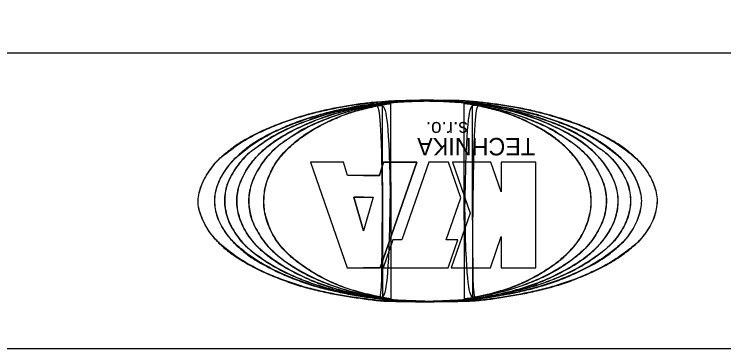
# Model space of a CAD drawing. Extents: x -728476.8 to -728424.3, y -1073086.9 to -1073012.7.
# Drawn here: x -728468.69 to -728456.69, y -1073048.15 to -1073042.49 of the extents above; entities that cross this region are included whole.
import ezdxf

# ---------------------------------------------------------------- set-up
doc = ezdxf.new("R2010")
doc.units = 0
doc.layers.add('A1_OBVOD Spravy železnic', color=7, linetype='Continuous')
doc.layers.add('B6_JŽM', color=7, linetype='Continuous')

msp = doc.modelspace()

# ---------------------------------------------------------------- linework, layer by layer
at = {"layer": 'A1_OBVOD Spravy železnic'}
msp.add_line((-728429.288, -1073043.154), (-728471.788, -1073043.154), dxfattribs=at)
msp.add_lwpolyline([(-728429.288, -1073048.154), (-728471.788, -1073048.154), (-728471.788, -1073035.654), (-728429.288, -1073035.654)], close=True, dxfattribs=at)
at = {"layer": 'B6_JŽM'}
for p, q in [((-728462.947, -1073045.587), (-728462.781, -1073045.587)), ((-728462.781, -1073046.161), (-728462.947, -1073045.587))]:
    msp.add_line(p, q, dxfattribs=at)
for points in [[(-728462.781, -1073045.225), (-728463.051, -1073045.225), (-728463.117, -1073044.997), (-728463.68, -1073044.998), (-728463.059, -1073046.782), (-728462.781, -1073046.782)], [(-728462.781, -1073045.225), (-728463.051, -1073045.225), (-728463.117, -1073044.997), (-728463.68, -1073044.998), (-728463.059, -1073046.782), (-728462.781, -1073046.782)], [(-728462.781, -1073045.225), (-728462.51, -1073045.225), (-728462.444, -1073044.997), (-728461.881, -1073044.998), (-728462.502, -1073046.782), (-728462.781, -1073046.782)], [(-728462.781, -1073046.782), (-728462.502, -1073046.782), (-728461.881, -1073044.998), (-728462.444, -1073044.997), (-728462.51, -1073045.225), (-728462.781, -1073045.225)], [(-728461.351, -1073046.782), (-728461.187, -1073046.311), (-728461.381, -1073046.311), (-728461.134, -1073045.601), (-728461.344, -1073044.997), (-728461.676, -1073044.997), (-728462.133, -1073046.311), (-728462.284, -1073046.311), (-728462.449, -1073046.782), (-728461.351, -1073046.782)], [(-728461.351, -1073046.782), (-728461.187, -1073046.311), (-728461.381, -1073046.311), (-728461.134, -1073045.601), (-728461.344, -1073044.997), (-728461.676, -1073044.997), (-728462.133, -1073046.311), (-728462.284, -1073046.311), (-728462.449, -1073046.782), (-728461.351, -1073046.782)], [(-728459.867, -1073046.782), (-728459.867, -1073044.997), (-728460.451, -1073044.997), (-728460.451, -1073045.5), (-728460.626, -1073044.997), (-728461.276, -1073044.997), (-728460.976, -1073045.859), (-728461.297, -1073046.782), (-728460.635, -1073046.782), (-728460.451, -1073046.253), (-728460.451, -1073046.782), (-728459.867, -1073046.782)], [(-728459.867, -1073046.782), (-728459.867, -1073044.997), (-728460.451, -1073044.997), (-728460.451, -1073045.5), (-728460.626, -1073044.997), (-728461.276, -1073044.997), (-728460.976, -1073045.859), (-728461.297, -1073046.782), (-728460.635, -1073046.782), (-728460.451, -1073046.253), (-728460.451, -1073046.782), (-728459.867, -1073046.782)], [(-728462.781, -1073045.587), (-728462.947, -1073045.587), (-728462.781, -1073046.161)], [(-728462.781, -1073045.587), (-728462.615, -1073045.587), (-728462.781, -1073046.161)], [(-728462.781, -1073045.587), (-728462.615, -1073045.587), (-728462.781, -1073046.161)]]:
    msp.add_lwpolyline(points, dxfattribs=at)
for points in [[(-728462.313, -1073043.965), (-728462.376, -1073043.969), (-728462.529, -1073043.98), (-728462.771, -1073044), (-728463.038, -1073044.044), (-728463.307, -1073044.089), (-728463.576, -1073044.15), (-728463.845, -1073044.224), (-728464.113, -1073044.313), (-728464.382, -1073044.416), (-728464.653, -1073044.542), (-728464.929, -1073044.699), (-728465.125, -1073044.86), (-728465.283, -1073044.992), (-728465.368, -1073045.112), (-728465.461, -1073045.242), (-728465.521, -1073045.38), (-728465.567, -1073045.514), (-728465.592, -1073045.65), (-728465.574, -1073045.789), (-728465.523, -1073045.921), (-728465.466, -1073046.059), (-728465.382, -1073046.195), (-728465.284, -1073046.308), (-728465.134, -1073046.456), (-728464.928, -1073046.611), (-728464.655, -1073046.771), (-728464.385, -1073046.901), (-728464.114, -1073047.001), (-728463.847, -1073047.097), (-728463.576, -1073047.164), (-728463.308, -1073047.226), (-728463.038, -1073047.272), (-728462.769, -1073047.307), (-728462.502, -1073047.348), (-728462.234, -1073047.351), (-728461.966, -1073047.357), (-728461.788, -1073047.358), (-728461.698, -1073047.359)], [(-728461.698, -1073047.359), (-728461.395, -1073047.355), (-728461.162, -1073047.352), (-728460.894, -1073047.341), (-728460.626, -1073047.312), (-728460.358, -1073047.27), (-728460.09, -1073047.224), (-728459.822, -1073047.166), (-728459.554, -1073047.096), (-728459.285, -1073047.009), (-728459.017, -1073046.902), (-728458.751, -1073046.779), (-728458.482, -1073046.62), (-728458.214, -1073046.418), (-728458.11, -1073046.321), (-728458.001, -1073046.186), (-728457.919, -1073046.053), (-728457.859, -1073045.918), (-728457.827, -1073045.785), (-728457.811, -1073045.651), (-728457.825, -1073045.519), (-728457.866, -1073045.383), (-728457.926, -1073045.249), (-728458.01, -1073045.115), (-728458.118, -1073044.981), (-728458.214, -1073044.891), (-728458.482, -1073044.688), (-728458.75, -1073044.537), (-728459.015, -1073044.413), (-728459.286, -1073044.311), (-728459.555, -1073044.224), (-728459.821, -1073044.151), (-728460.088, -1073044.092), (-728460.357, -1073044.043), (-728460.626, -1073044.005), (-728460.895, -1073043.975), (-728461.16, -1073043.957), (-728461.43, -1073043.954), (-728461.698, -1073043.95), (-728461.966, -1073043.954), (-728462.235, -1073043.961), (-728462.503, -1073043.978), (-728462.769, -1073044.003), (-728463.038, -1073044.044), (-728463.306, -1073044.092), (-728463.574, -1073044.152), (-728463.843, -1073044.226), (-728464.111, -1073044.314), (-728464.379, -1073044.418), (-728464.645, -1073044.543), (-728464.915, -1073044.701), (-728465.185, -1073044.91), (-728465.265, -1073044.981), (-728465.37, -1073045.115), (-728465.458, -1073045.248), (-728465.52, -1073045.383), (-728465.564, -1073045.516), (-728465.585, -1073045.651), (-728465.57, -1073045.784), (-728465.523, -1073045.919), (-728465.463, -1073046.056), (-728465.383, -1073046.186), (-728465.269, -1073046.321), (-728465.187, -1073046.402), (-728464.916, -1073046.612), (-728464.648, -1073046.77), (-728464.382, -1073046.897), (-728464.112, -1073047.001), (-728463.843, -1073047.093), (-728463.576, -1073047.163), (-728463.306, -1073047.224), (-728463.037, -1073047.27), (-728462.768, -1073047.308), (-728462.502, -1073047.342), (-728462.234, -1073047.352), (-728461.967, -1073047.356), (-728461.698, -1073047.359), (-728461.698, -1073047.359), (-728461.698, -1073047.359)], [(-728461.698, -1073047.352), (-728461.788, -1073047.348), (-728461.967, -1073047.341), (-728462.235, -1073047.338), (-728462.503, -1073047.309), (-728462.771, -1073047.275), (-728463.04, -1073047.23), (-728463.307, -1073047.171), (-728463.578, -1073047.107), (-728463.845, -1073047.015), (-728464.116, -1073046.912), (-728464.383, -1073046.78), (-728464.662, -1073046.63), (-728464.867, -1073046.466), (-728465.02, -1073046.314), (-728465.116, -1073046.192), (-728465.198, -1073046.057), (-728465.26, -1073045.922), (-728465.292, -1073045.785), (-728465.303, -1073045.65), (-728465.293, -1073045.514), (-728465.252, -1073045.379), (-728465.192, -1073045.244), (-728465.107, -1073045.11), (-728465.016, -1073044.991), (-728464.861, -1073044.846), (-728464.662, -1073044.681), (-728464.385, -1073044.525), (-728464.114, -1073044.4), (-728463.845, -1073044.295), (-728463.576, -1073044.211), (-728463.308, -1073044.136), (-728463.039, -1073044.081), (-728462.771, -1073044.032), (-728462.502, -1073044.005), (-728462.234, -1073043.982), (-728461.967, -1073043.965), (-728461.698, -1073043.956), (-728461.43, -1073043.967), (-728461.162, -1073043.986), (-728460.893, -1073044), (-728460.625, -1073044.032), (-728460.356, -1073044.076), (-728460.088, -1073044.133), (-728459.818, -1073044.199), (-728459.552, -1073044.291), (-728459.281, -1073044.388), (-728459.009, -1073044.512), (-728458.74, -1073044.675), (-728458.528, -1073044.835), (-728458.367, -1073044.983), (-728458.27, -1073045.109), (-728458.191, -1073045.245), (-728458.13, -1073045.38), (-728458.093, -1073045.515), (-728458.069, -1073045.651), (-728458.09, -1073045.787), (-728458.125, -1073045.922), (-728458.181, -1073046.057), (-728458.261, -1073046.192), (-728458.357, -1073046.324), (-728458.525, -1073046.473), (-728458.736, -1073046.641), (-728459.014, -1073046.789), (-728459.281, -1073046.919), (-728459.55, -1073047.024), (-728459.819, -1073047.109), (-728460.088, -1073047.178), (-728460.317, -1073047.224), (-728460.497, -1073047.257), (-728460.675, -1073047.285), (-728460.893, -1073047.317), (-728461.162, -1073047.334), (-728461.43, -1073047.345), (-728461.609, -1073047.349), (-728461.698, -1073047.352)], [(-728461.698, -1073047.352), (-728461.43, -1073047.344), (-728461.162, -1073047.333), (-728460.894, -1073047.314), (-728460.626, -1073047.277), (-728460.506, -1073047.258), (-728460.358, -1073047.231), (-728460.09, -1073047.176), (-728459.822, -1073047.107), (-728459.553, -1073047.021), (-728459.285, -1073046.916), (-728459.017, -1073046.789), (-728458.751, -1073046.639), (-728458.482, -1073046.434), (-728458.363, -1073046.321), (-728458.26, -1073046.186), (-728458.183, -1073046.053), (-728458.127, -1073045.918), (-728458.092, -1073045.785), (-728458.077, -1073045.651), (-728458.095, -1073045.517), (-728458.133, -1073045.384), (-728458.192, -1073045.249), (-728458.27, -1073045.115), (-728458.376, -1073044.98), (-728458.482, -1073044.879), (-728458.75, -1073044.675), (-728459.017, -1073044.514), (-728459.285, -1073044.391), (-728459.553, -1073044.291), (-728459.821, -1073044.203), (-728460.089, -1073044.134), (-728460.357, -1073044.078), (-728460.626, -1073044.034), (-728460.894, -1073044.003), (-728461.162, -1073043.985), (-728461.43, -1073043.968), (-728461.698, -1073043.96), (-728461.966, -1073043.967), (-728462.235, -1073043.983), (-728462.501, -1073044.006), (-728462.769, -1073044.035), (-728463.038, -1073044.082), (-728463.306, -1073044.139), (-728463.574, -1073044.212), (-728463.843, -1073044.298), (-728464.111, -1073044.402), (-728464.379, -1073044.526), (-728464.647, -1073044.683), (-728464.915, -1073044.897), (-728465.001, -1073044.981), (-728465.108, -1073045.115), (-728465.19, -1073045.248), (-728465.251, -1073045.383), (-728465.289, -1073045.516), (-728465.3, -1073045.649), (-728465.288, -1073045.785), (-728465.256, -1073045.918), (-728465.197, -1073046.052), (-728465.116, -1073046.186), (-728465.009, -1073046.321), (-728464.915, -1073046.416), (-728464.647, -1073046.628), (-728464.379, -1073046.78), (-728464.111, -1073046.909), (-728463.843, -1073047.014), (-728463.575, -1073047.103), (-728463.307, -1073047.17), (-728463.039, -1073047.228), (-728462.77, -1073047.273), (-728462.502, -1073047.308), (-728462.235, -1073047.334), (-728461.967, -1073047.342), (-728461.698, -1073047.352), (-728461.698, -1073047.352), (-728461.698, -1073047.352)], [(-728461.698, -1073047.359), (-728461.597, -1073047.357), (-728461.419, -1073047.355), (-728461.15, -1073047.352), (-728460.893, -1073047.344), (-728460.625, -1073047.315), (-728460.358, -1073047.27), (-728460.089, -1073047.226), (-728459.82, -1073047.168), (-728459.551, -1073047.099), (-728459.282, -1073047.011), (-728459.015, -1073046.903), (-728458.743, -1073046.781), (-728458.472, -1073046.62), (-728458.261, -1073046.462), (-728458.1, -1073046.316), (-728458.001, -1073046.193), (-728457.918, -1073046.057), (-728457.855, -1073045.923), (-728457.825, -1073045.786), (-728457.805, -1073045.652), (-728457.822, -1073045.515), (-728457.864, -1073045.38), (-728457.924, -1073045.244), (-728458.012, -1073045.11), (-728458.106, -1073044.988), (-728458.264, -1073044.845), (-728458.469, -1073044.686), (-728458.744, -1073044.536), (-728459.012, -1073044.41), (-728459.283, -1073044.31), (-728459.552, -1073044.222), (-728459.82, -1073044.149), (-728460.088, -1073044.09), (-728460.356, -1073044.041), (-728460.626, -1073044.004), (-728460.893, -1073043.974), (-728461.162, -1073043.953), (-728461.43, -1073043.956), (-728461.698, -1073043.947), (-728461.966, -1073043.955), (-728462.171, -1073043.958), (-728462.287, -1073043.964), (-728462.313, -1073043.965)], [(-728462.458, -1073044.009), (-728462.509, -1073044.014), (-728462.614, -1073044.022), (-728462.809, -1073044.052), (-728463.041, -1073044.1), (-728463.312, -1073044.158), (-728463.579, -1073044.243), (-728463.848, -1073044.336), (-728464.118, -1073044.453), (-728464.392, -1073044.6), (-728464.582, -1073044.75), (-728464.752, -1073044.861), (-728464.852, -1073044.974), (-728464.954, -1073045.111), (-728465.034, -1073045.245), (-728465.096, -1073045.378), (-728465.123, -1073045.516), (-728465.138, -1073045.65), (-728465.123, -1073045.786), (-728465.092, -1073045.922), (-728465.04, -1073046.06), (-728464.957, -1073046.19), (-728464.861, -1073046.332), (-728464.751, -1073046.438), (-728464.591, -1073046.568), (-728464.389, -1073046.71), (-728464.118, -1073046.863), (-728463.846, -1073046.976), (-728463.579, -1073047.078), (-728463.309, -1073047.151), (-728463.038, -1073047.212), (-728462.771, -1073047.265), (-728462.577, -1073047.299), (-728462.473, -1073047.306), (-728462.459, -1073047.306)], [(-728462.458, -1073044.009), (-728462.611, -1073044.024), (-728462.772, -1073044.048), (-728463.04, -1073044.1), (-728463.309, -1073044.162), (-728463.578, -1073044.244), (-728463.845, -1073044.339), (-728464.112, -1073044.454), (-728464.381, -1073044.603), (-728464.65, -1073044.794), (-728464.722, -1073044.845), (-728464.854, -1073044.98), (-728464.955, -1073045.117), (-728465.033, -1073045.249), (-728465.091, -1073045.381), (-728465.121, -1073045.517), (-728465.133, -1073045.651), (-728465.121, -1073045.783), (-728465.09, -1073045.919), (-728465.037, -1073046.054), (-728464.958, -1073046.187), (-728464.862, -1073046.321), (-728464.725, -1073046.458), (-728464.652, -1073046.518), (-728464.381, -1073046.709), (-728464.11, -1073046.86), (-728463.843, -1073046.976), (-728463.578, -1073047.073), (-728463.304, -1073047.15), (-728463.039, -1073047.21), (-728462.769, -1073047.264), (-728462.501, -1073047.304), (-728462.459, -1073047.306), (-728462.458, -1073044.009), (-728462.459, -1073047.306)], [(-728462.459, -1073047.306), (-728462.555, -1073047.292), (-728462.749, -1073047.263), (-728463.033, -1073047.204), (-728463.31, -1073047.128), (-728463.58, -1073047.039), (-728463.848, -1073046.921), (-728464.118, -1073046.779), (-728464.355, -1073046.624), (-728464.541, -1073046.469), (-728464.665, -1073046.326), (-728464.763, -1073046.193), (-728464.835, -1073046.057), (-728464.887, -1073045.922), (-728464.917, -1073045.786), (-728464.927, -1073045.65), (-728464.917, -1073045.515), (-728464.883, -1073045.379), (-728464.825, -1073045.246), (-728464.755, -1073045.108), (-728464.654, -1073044.976), (-728464.531, -1073044.837), (-728464.352, -1073044.682), (-728464.118, -1073044.53), (-728463.846, -1073044.393), (-728463.577, -1073044.279), (-728463.31, -1073044.183), (-728463.04, -1073044.111), (-728462.797, -1073044.062), (-728462.603, -1073044.029), (-728462.498, -1073044.015), (-728462.458, -1073044.009)], [(-728462.459, -1073047.306), (-728462.748, -1073047.26), (-728463.038, -1073047.2), (-728463.308, -1073047.126), (-728463.577, -1073047.035), (-728463.842, -1073046.92), (-728464.11, -1073046.778), (-728464.379, -1073046.6), (-728464.547, -1073046.455), (-728464.667, -1073046.32), (-728464.762, -1073046.187), (-728464.833, -1073046.055), (-728464.884, -1073045.919), (-728464.914, -1073045.783), (-728464.923, -1073045.651), (-728464.913, -1073045.516), (-728464.88, -1073045.383), (-728464.825, -1073045.249), (-728464.753, -1073045.114), (-728464.655, -1073044.981), (-728464.536, -1073044.847), (-728464.376, -1073044.708), (-728464.111, -1073044.532), (-728463.842, -1073044.394), (-728463.574, -1073044.28), (-728463.306, -1073044.186), (-728463.039, -1073044.114), (-728462.77, -1073044.058), (-728462.58, -1073044.027), (-728462.458, -1073044.009), (-728462.459, -1073047.306), (-728462.458, -1073044.009)], [(-728462.318, -1073044.005), (-728462.379, -1073044.011), (-728462.532, -1073044.024), (-728462.771, -1073044.075), (-728463.042, -1073044.136), (-728463.309, -1073044.228), (-728463.579, -1073044.332), (-728463.853, -1073044.462), (-728464.055, -1073044.605), (-728464.235, -1073044.724), (-728464.353, -1073044.841), (-728464.475, -1073044.972), (-728464.558, -1073045.113), (-728464.635, -1073045.244), (-728464.687, -1073045.379), (-728464.715, -1073045.515), (-728464.73, -1073045.65), (-728464.714, -1073045.785), (-728464.693, -1073045.922), (-728464.637, -1073046.056), (-728464.565, -1073046.19), (-728464.478, -1073046.327), (-728464.365, -1073046.464), (-728464.237, -1073046.578), (-728464.062, -1073046.71), (-728463.851, -1073046.848), (-728463.58, -1073046.981), (-728463.31, -1073047.086), (-728463.042, -1073047.175), (-728462.772, -1073047.236), (-728462.532, -1073047.286), (-728462.379, -1073047.303), (-728462.318, -1073047.31)], [(-728462.318, -1073044.005), (-728462.502, -1073044.024), (-728462.771, -1073044.075), (-728463.037, -1073044.14), (-728463.306, -1073044.229), (-728463.575, -1073044.335), (-728463.842, -1073044.466), (-728464.111, -1073044.641), (-728464.212, -1073044.712), (-728464.358, -1073044.848), (-728464.473, -1073044.98), (-728464.559, -1073045.115), (-728464.633, -1073045.249), (-728464.684, -1073045.383), (-728464.713, -1073045.514), (-728464.725, -1073045.65), (-728464.713, -1073045.786), (-728464.688, -1073045.918), (-728464.637, -1073046.051), (-728464.564, -1073046.188), (-728464.479, -1073046.321), (-728464.367, -1073046.455), (-728464.22, -1073046.589), (-728464.11, -1073046.673), (-728463.842, -1073046.846), (-728463.576, -1073046.979), (-728463.306, -1073047.085), (-728463.04, -1073047.171), (-728462.772, -1073047.235), (-728462.502, -1073047.287), (-728462.318, -1073047.31), (-728462.318, -1073044.005), (-728462.318, -1073047.31)], [(-728462.318, -1073047.31), (-728462.379, -1073047.301), (-728462.532, -1073047.279), (-728462.772, -1073047.22), (-728463.043, -1073047.148), (-728463.313, -1073047.042), (-728463.583, -1073046.903), (-728463.819, -1073046.749), (-728464.012, -1073046.6), (-728464.148, -1073046.461), (-728464.254, -1073046.327), (-728464.335, -1073046.191), (-728464.393, -1073046.055), (-728464.437, -1073045.921), (-728464.465, -1073045.786), (-728464.469, -1073045.651), (-728464.461, -1073045.516), (-728464.435, -1073045.38), (-728464.387, -1073045.247), (-728464.328, -1073045.11), (-728464.243, -1073044.977), (-728464.137, -1073044.841), (-728464.001, -1073044.708), (-728463.817, -1073044.555), (-728463.583, -1073044.408), (-728463.312, -1073044.274), (-728463.043, -1073044.165), (-728462.773, -1073044.09), (-728462.531, -1073044.039), (-728462.379, -1073044.015), (-728462.318, -1073044.005)], [(-728462.318, -1073047.31), (-728462.502, -1073047.281), (-728462.77, -1073047.219), (-728463.039, -1073047.143), (-728463.307, -1073047.04), (-728463.575, -1073046.902), (-728463.843, -1073046.728), (-728464.019, -1073046.588), (-728464.149, -1073046.455), (-728464.254, -1073046.32), (-728464.333, -1073046.187), (-728464.392, -1073046.053), (-728464.435, -1073045.919), (-728464.461, -1073045.784), (-728464.467, -1073045.651), (-728464.458, -1073045.517), (-728464.432, -1073045.382), (-728464.386, -1073045.249), (-728464.326, -1073045.115), (-728464.243, -1073044.981), (-728464.139, -1073044.849), (-728464.004, -1073044.714), (-728463.843, -1073044.581), (-728463.575, -1073044.41), (-728463.307, -1073044.276), (-728463.04, -1073044.169), (-728462.769, -1073044.092), (-728462.502, -1073044.036), (-728462.318, -1073044.005), (-728462.318, -1073047.31), (-728462.318, -1073044.005)], [(-728461.079, -1073044.005), (-728461.017, -1073044.011), (-728460.864, -1073044.024), (-728460.625, -1073044.075), (-728460.355, -1073044.136), (-728460.088, -1073044.228), (-728459.817, -1073044.332), (-728459.543, -1073044.462), (-728459.341, -1073044.605), (-728459.162, -1073044.724), (-728459.043, -1073044.841), (-728458.921, -1073044.972), (-728458.839, -1073045.113), (-728458.762, -1073045.244), (-728458.71, -1073045.379), (-728458.681, -1073045.515), (-728458.667, -1073045.65), (-728458.683, -1073045.785), (-728458.704, -1073045.922), (-728458.759, -1073046.056), (-728458.831, -1073046.19), (-728458.918, -1073046.327), (-728459.031, -1073046.464), (-728459.16, -1073046.578), (-728459.334, -1073046.71), (-728459.545, -1073046.848), (-728459.817, -1073046.981), (-728460.086, -1073047.086), (-728460.354, -1073047.175), (-728460.624, -1073047.236), (-728460.865, -1073047.286), (-728461.017, -1073047.303), (-728461.079, -1073047.31)], [(-728461.079, -1073047.31), (-728461.017, -1073047.301), (-728460.865, -1073047.279), (-728460.625, -1073047.22), (-728460.354, -1073047.148), (-728460.083, -1073047.042), (-728459.814, -1073046.903), (-728459.577, -1073046.749), (-728459.384, -1073046.6), (-728459.249, -1073046.461), (-728459.142, -1073046.327), (-728459.061, -1073046.191), (-728459.003, -1073046.055), (-728458.96, -1073045.921), (-728458.932, -1073045.786), (-728458.928, -1073045.651), (-728458.936, -1073045.516), (-728458.962, -1073045.38), (-728459.01, -1073045.247), (-728459.069, -1073045.11), (-728459.153, -1073044.977), (-728459.26, -1073044.841), (-728459.395, -1073044.708), (-728459.579, -1073044.555), (-728459.813, -1073044.408), (-728460.084, -1073044.274), (-728460.353, -1073044.165), (-728460.624, -1073044.09), (-728460.866, -1073044.039), (-728461.017, -1073044.015), (-728461.079, -1073044.005)], [(-728461.079, -1073044.005), (-728460.894, -1073044.024), (-728460.625, -1073044.075), (-728460.359, -1073044.14), (-728460.09, -1073044.229), (-728459.821, -1073044.335), (-728459.554, -1073044.466), (-728459.286, -1073044.641), (-728459.185, -1073044.712), (-728459.039, -1073044.848), (-728458.923, -1073044.98), (-728458.838, -1073045.115), (-728458.764, -1073045.249), (-728458.713, -1073045.383), (-728458.684, -1073045.514), (-728458.672, -1073045.65), (-728458.684, -1073045.786), (-728458.709, -1073045.918), (-728458.76, -1073046.051), (-728458.832, -1073046.188), (-728458.918, -1073046.321), (-728459.029, -1073046.455), (-728459.177, -1073046.589), (-728459.287, -1073046.673), (-728459.554, -1073046.846), (-728459.821, -1073046.979), (-728460.09, -1073047.085), (-728460.356, -1073047.171), (-728460.625, -1073047.235), (-728460.894, -1073047.287), (-728461.079, -1073047.31), (-728461.079, -1073044.005), (-728461.079, -1073047.31)], [(-728461.079, -1073047.31), (-728460.894, -1073047.281), (-728460.627, -1073047.219), (-728460.357, -1073047.143), (-728460.09, -1073047.04), (-728459.821, -1073046.902), (-728459.554, -1073046.728), (-728459.378, -1073046.588), (-728459.248, -1073046.455), (-728459.142, -1073046.32), (-728459.063, -1073046.187), (-728459.005, -1073046.053), (-728458.962, -1073045.919), (-728458.936, -1073045.784), (-728458.93, -1073045.651), (-728458.939, -1073045.517), (-728458.965, -1073045.382), (-728459.01, -1073045.249), (-728459.07, -1073045.115), (-728459.154, -1073044.981), (-728459.258, -1073044.849), (-728459.392, -1073044.714), (-728459.553, -1073044.581), (-728459.821, -1073044.41), (-728460.089, -1073044.276), (-728460.357, -1073044.169), (-728460.628, -1073044.092), (-728460.894, -1073044.036), (-728461.079, -1073044.005), (-728461.079, -1073047.31), (-728461.079, -1073044.005)], [(-728460.938, -1073047.306), (-728460.841, -1073047.292), (-728460.647, -1073047.263), (-728460.363, -1073047.204), (-728460.087, -1073047.128), (-728459.816, -1073047.039), (-728459.549, -1073046.921), (-728459.278, -1073046.779), (-728459.041, -1073046.624), (-728458.855, -1073046.469), (-728458.731, -1073046.326), (-728458.634, -1073046.193), (-728458.562, -1073046.057), (-728458.51, -1073045.922), (-728458.479, -1073045.786), (-728458.47, -1073045.65), (-728458.48, -1073045.515), (-728458.514, -1073045.379), (-728458.571, -1073045.246), (-728458.642, -1073045.108), (-728458.743, -1073044.976), (-728458.865, -1073044.837), (-728459.045, -1073044.682), (-728459.278, -1073044.53), (-728459.55, -1073044.393), (-728459.819, -1073044.279), (-728460.087, -1073044.183), (-728460.356, -1073044.111), (-728460.599, -1073044.062), (-728460.794, -1073044.029), (-728460.898, -1073044.015), (-728460.939, -1073044.009)], [(-728460.939, -1073044.009), (-728460.888, -1073044.014), (-728460.782, -1073044.022), (-728460.588, -1073044.052), (-728460.356, -1073044.1), (-728460.085, -1073044.158), (-728459.817, -1073044.243), (-728459.548, -1073044.336), (-728459.278, -1073044.453), (-728459.004, -1073044.6), (-728458.814, -1073044.75), (-728458.645, -1073044.861), (-728458.544, -1073044.974), (-728458.442, -1073045.111), (-728458.363, -1073045.245), (-728458.301, -1073045.378), (-728458.274, -1073045.516), (-728458.259, -1073045.65), (-728458.273, -1073045.786), (-728458.304, -1073045.922), (-728458.356, -1073046.06), (-728458.44, -1073046.19), (-728458.535, -1073046.332), (-728458.645, -1073046.438), (-728458.805, -1073046.568), (-728459.007, -1073046.71), (-728459.279, -1073046.863), (-728459.55, -1073046.976), (-728459.818, -1073047.078), (-728460.088, -1073047.151), (-728460.358, -1073047.212), (-728460.626, -1073047.265), (-728460.819, -1073047.299), (-728460.924, -1073047.306), (-728460.938, -1073047.306)], [(-728460.939, -1073044.009), (-728460.785, -1073044.024), (-728460.625, -1073044.048), (-728460.357, -1073044.1), (-728460.087, -1073044.162), (-728459.818, -1073044.244), (-728459.552, -1073044.339), (-728459.285, -1073044.454), (-728459.016, -1073044.603), (-728458.746, -1073044.794), (-728458.674, -1073044.845), (-728458.543, -1073044.98), (-728458.441, -1073045.117), (-728458.364, -1073045.249), (-728458.306, -1073045.381), (-728458.275, -1073045.517), (-728458.263, -1073045.651), (-728458.275, -1073045.783), (-728458.307, -1073045.919), (-728458.359, -1073046.054), (-728458.438, -1073046.187), (-728458.534, -1073046.321), (-728458.671, -1073046.458), (-728458.745, -1073046.518), (-728459.016, -1073046.709), (-728459.287, -1073046.86), (-728459.554, -1073046.976), (-728459.818, -1073047.073), (-728460.092, -1073047.15), (-728460.358, -1073047.21), (-728460.627, -1073047.264), (-728460.896, -1073047.304), (-728460.938, -1073047.306), (-728460.939, -1073044.009), (-728460.938, -1073047.306)], [(-728460.938, -1073047.306), (-728460.649, -1073047.26), (-728460.358, -1073047.2), (-728460.089, -1073047.126), (-728459.82, -1073047.035), (-728459.554, -1073046.92), (-728459.286, -1073046.778), (-728459.017, -1073046.6), (-728458.849, -1073046.455), (-728458.729, -1073046.32), (-728458.635, -1073046.187), (-728458.564, -1073046.055), (-728458.512, -1073045.919), (-728458.482, -1073045.783), (-728458.473, -1073045.651), (-728458.483, -1073045.516), (-728458.516, -1073045.383), (-728458.572, -1073045.249), (-728458.644, -1073045.114), (-728458.741, -1073044.981), (-728458.861, -1073044.847), (-728459.02, -1073044.708), (-728459.285, -1073044.532), (-728459.555, -1073044.394), (-728459.822, -1073044.28), (-728460.091, -1073044.186), (-728460.357, -1073044.114), (-728460.626, -1073044.058), (-728460.817, -1073044.027), (-728460.939, -1073044.009), (-728460.938, -1073047.306), (-728460.939, -1073044.009)]]:
    msp.add_open_spline(points, degree=3, dxfattribs=at)

# ---------------------------------------------------------------- texts
for s, height, p in [('s.r.o.', 0.2386, (-728461.018, -1073044.318)), ('TECHNIKA', 0.2949, (-728459.879, -1073044.587))]:
    msp.add_text(s, height=height, rotation=180, dxfattribs=at).set_placement(p)

doc.saveas('drawing.dxf')
